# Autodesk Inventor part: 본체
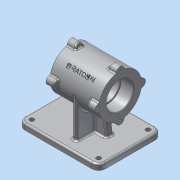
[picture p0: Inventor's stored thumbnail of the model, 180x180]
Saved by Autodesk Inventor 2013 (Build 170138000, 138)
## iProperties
Created: 2015-12
Part Number: 본체
Material: 알루미늄 6061
Document SubType Name: Modeling
Designer: dgall
Density: 2.71 g/cm^3
Mass: 1165.29 g
Surface Area: 815.622 cm^2
Volume: 429.997 cm^3
Author: dgall
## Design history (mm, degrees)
sketch "스케치1"
  geometry: L1 (-70, 55)-(70, 55); L2 (70, 55)-(70, -55); L3 (70, -55)-(-70, -55); L4 (-70, -55)-(-70, 55); 3 further points
  constraints: 8 end point, 2 midpoint, 2 parallel, 1 horizontal, 1 horizontal alignment, 1 perpendicular, 1 vertical alignment
  dimensions: "d0" = 140 distance of L1.start L1.end; "d2" = 110 distance of L1.end L2.end
extrude "돌출1" new body sketch "스케치1" distance "d3" = 10; taper "d4" = 0 deg
node "작업 평면1"
sketch "스케치2"
  geometry: L1 (0, 110)-(0, 0) reference; L2 (0, 0)-(-10, 0) reference; L3 (-10, 110)-(-10, 0) reference; L4 (0, 110)-(-10, 110) reference; C1 r 37 at (70, 55); 2 further points
  constraints: 1 centre point, 1 horizontal alignment, 1 midpoint
  dimensions: "d6" = 74 diameter of C1; "d8" = 80 distance from line of L3 C1.centre
extrude "돌출2" join sketch "스케치2" stored distance "d9" = 85; taper "d10" = 0 deg
node "작업 평면2"
sketch "스케치3"
  geometry: L1 (37.5, 107)-(37.5, 33) reference; L2 (122.5, 33)-(122.5, 107) reference; L3 (37.5, 70)-(122.5, 70); L4 (37.5, 93.5)-(59.5, 93.5); L5 (59.5, 93.5)-(59.5, 91); L6 (59.5, 91)-(100.5, 91); L7 (100.5, 91)-(100.5, 93.5); L8 (100.5, 93.5)-(122.5, 93.5); L9 (37.5, 33)-(122.5, 33) reference; 2 further points
  constraints: 12 end point, 3 midpoint, 3 parallel, 2 perpendicular, 2 point on line
  dimensions: "d11" = 47 diameter of L4 L3; "d13" = 42 diameter of L6 L3; "d14" = 47 diameter of L8 L3; "d15" = 22 distance of L7.end L8.end; "d16" = 22 distance of L4.start L4.end
revolve "회전1" sketch "스케치3" stored, may be unused: angle "d17" = 90 deg
sketch "스케치4"
  geometry: L1 (37.5, 107)-(37.5, 33) reference; L2 (122.5, 33)-(122.5, 107) reference; L3 (37.5, 33)-(122.5, 33) reference; L4 (80, 33)-(80, 0); L5 (59.706, 38.325)-(55, 0); L6 (100.294, 38.325)-(105, 0); L7 (0, 0)-(140, 0) reference; L8 (59.706, 38.325)-(100.294, 38.325); 1 further point
  constraints: 8 end point, 3 point on line, 1 midpoint, 1 parallel, 1 perpendicular
  dimensions: "d21" = 97 deg angle of L7 L5; "d22" = 97 deg angle of L7 L6; "d23" = 25 distance of L5.end L4.end; "d24" = 50 distance of L6.end L5.end
extrude "돌출3" join sketch "스케치4" stored distance "d25" = 12; taper "d26" = 0 deg
node "작업 평면3"
sketch "스케치5"
  geometry: L1 (61, 0)-(61, 33.49) reference; L2 (49, 0)-(61, 0) reference; L3 (49, 33.49)-(49, 0) reference; L4 (0, 0)-(110, 0) reference; L5 (110, 0)-(110, -10) reference; L6 (0, -10)-(110, -10) reference; L7 (0, 0)-(0, -10) reference; L8 (55, 70)-(55, 0); L9 (18, 70)-(18, 0); L10 (92, 70)-(92, 0); C1 r 23.5 at (55, 70) reference; C2 r 37 at (55, 70) reference; A1 r 37 centre (55, 70) between (49, 33.49) and (61, 33.49) reference; A2 r 37 centre (55, 70) between (18, 70) and (92, 70); 1 further point
  constraints: 6 end point, 2 point on circle, 2 point on line, 1 centre point, 1 coincident, 1 concentric, 1 midpoint, 1 parallel
  dimensions: "d28" = 37 distance between parallel lines of L8 L9; "d30" = 74 distance between parallel lines of L10 L9
extrude "돌출4" join sketch "스케치5" stored distance "d31" = 8; taper "d32" = 0 deg
sketch "스케치6"
  geometry: C1 r 23.5 at (0, 0) reference; C2 r 37 at (0, 0) reference; 1 further point
node "작업 평면4"
sketch "스케치7"
  geometry: L1 (37.5, 107)-(122.5, 107) reference; L2 (122.5, 33)-(122.5, 107) reference; L3 (122.5, 107)-(122.5, 114); L4 (122.5, 114)-(110.048, 114); L5 (110.048, 114)-(105.405, 101.245); L6 (122.5, 101.245)-(105.405, 101.245); 1 further point
  constraints: 8 end point, 1 collinear, 1 parallel, 1 perpendicular, 1 point on line
  dimensions: "d35" = 7 distance of L1.end L3.end
extrude "돌출5" join sketch "스케치7" stored distance "d36" = 14; taper "d37" = 0 deg
fillet "모깎기1" dims "d38" = 7
sketch "스케치8"
  geometry: C1 r 23.5 at (-55, 70) reference; C2 r 37 at (-55, 70); C3 r 2 at (-55, 107); A1 r 7 centre (-55, 107) between (-48, 107) and (-62, 107) reference; 1 further point
  constraints: 2 centre point, 2 coincident
  dimensions: "d39" = 74 diameter of C2; "d40" = 4 diameter of C3
hole "구멍1" sketch "스케치8" at (-55, 107) diameter "d41" = 3.242; stored, may be unused: countersink angle "d45" = 90 deg, drill point angle "d47" = 118 deg; dims "d42" = 9, "d43" = 4, "d44" = 2, "d46" = 11
sketch "스케치9"
  geometry: L1 (37.5, 107)-(107.5, 107) reference; L2 (107.5, 107)-(110.048, 114) reference; L3 (122.5, 114)-(110.048, 114) reference; L4 (122.5, 114)-(122.5, 107) reference; 1 further point
fillet "모깎기2" dims "d51" = 3
sketch "스케치10"
  geometry: L1 (-32.5, 107)-(35.399, 107) reference; L2 (-32.5, 107)-(-32.5, 114); L3 (-32.5, 114)-(-20.048, 114); L4 (-20.048, 114)-(-16.185, 103.387); L5 (-16.185, 103.387)-(-32.5, 103.387); L6 (-32.5, 107)-(-32.5, 103.387); 1 further point
  constraints: 10 end point, 3 perpendicular, 1 parallel
  dimensions: "d55" = 7 distance between parallel lines of L3 L1; "d57" = 110 deg angle of L1 L4
extrude "돌출6" join sketch "스케치10" stored distance "d58" = 14; taper "d59" = 0 deg
sketch "스케치11" dims "d60" = 74
  geometry: C1 r 23.5 at (55, 70) reference; C2 r 2 at (55, 107); 2 further points
  constraints: 1 centre point, 1 coincident, 1 vertical alignment, 2 other
  dimensions: "d61" = 4 diameter of C2
hole "구멍2" sketch "스케치11" at (55, 107) diameter "d62" = 3.242; stored, may be unused: countersink angle "d66" = 90 deg, drill point angle "d68" = 118 deg; dims "d63" = 9, "d64" = 4, "d65" = 2, "d67" = 11
fillet "모깎기3" dims "d69" = 7
fillet "모깎기4" dims "d73" = 3
sketch "스케치12"
  geometry: L1 (-70, 55)-(70, 55) reference; L2 (-70, -55)-(-70, 55) reference; C1 r 4 at (-58, 43); 1 further point
  constraints: 1 centre point
  dimensions: "d77" = 8 diameter of C1; "d79" = 12 distance from line of L2 C1.centre; "d80" = 12 distance from line of L1 C1.centre
extrude "돌출7" cut sketch "스케치12" stored distance "d81" = 14; taper "d82" = 0 deg
fillet "모깎기5" dims "d89" = 12
fillet "모깎기6" dims "d90" = 3
fillet "모깎기7" dims "d91" = 3
fillet "모깎기8" dims "d92" = 0.3
chamfer "모따기1" distance "d93" = 1; stored, may be unused: second distance "d94" = 2, angle "d95" = 45 deg
node "작업 평면5"
sketch "스케치13"
  geometry: 1 further point
sketch "스케치14"
  geometry: L1 (-70, 55)-(-70, 4.362); L2 (-70, 55)-(-96.163, 28.837); 1 further point
  constraints: 4 end point, 1 vertical
  dimensions: "d97" = 45 deg angle of L1 L2
node "작업 평면6"
node "작업 평면7"
sketch "스케치16"
  geometry: 1 further point
sketch "스케치17"
  geometry: L1 (70, 55)-(70, 104.411); L2 (70, 55)-(96.163, 81.163); C1 r 21 at (70, 55) reference; 1 further point
  constraints: 4 end point, 1 coincident, 1 vertical
  dimensions: "d103" = 45 deg angle of L1 L2
node "작업 평면8"
sketch "스케치18"
  geometry: L1 (-42.5, 18.921)-(-42.5, -18.921) reference; L2 (42.5, -18.921)-(42.5, 18.921) reference; 3 further points
  constraints: 1 horizontal alignment, 1 midpoint, 1 other
  dimensions: "d105" = 42.5 distance from line of point (0, 0) L2
feature "엠보싱2" sketch "스케치18" dims "d106" = 0.5, "d107" = 0
node "솔리드1"
pattern_circular "원형 패턴1" dims "d49" = 360 deg
pattern_circular "원형 패턴2" dims angle "d53" = 360 deg
pattern_circular "원형 패턴3" dims "d71" = 360 deg
pattern_circular "원형 패턴4" dims angle "d75" = 360 deg
pattern_linear "직사각형 패턴1" dims "d85" = 116, "d88" = 86
node "투영된 루프1"
node "투영된 루프2"
node "투영된 루프3"
node "투영된 루프4"
node "투영된 루프5"
node "투영된 루프6"
other parameters: "d96" = -42.5, "d101" = -42.5
